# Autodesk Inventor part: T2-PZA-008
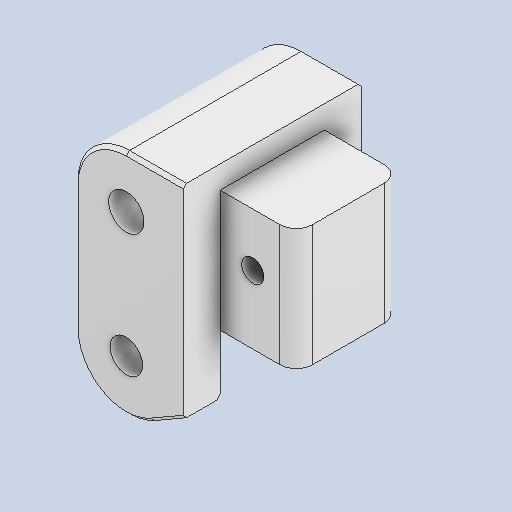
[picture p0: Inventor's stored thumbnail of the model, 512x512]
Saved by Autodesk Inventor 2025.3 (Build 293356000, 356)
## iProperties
Created: 2026-10
Part Number: T2-PZA-008
Material: Genérico
Description: Eslabón distal
Document SubType Name: Modeling
Designer: Luis MuÃ±oz
Density: 1 g/cm^3
Appearance: Valor por defecto
Project: TESIS 2 - Plataforma mecatrÃ³nica preventiva desacoplada
Sending System: ONSHAPE BY PTC INC, 1.194
Preprocessor: ST-DEVELOPER v20
Material_Fabricacion: PLA
Title: EslabÃ³n distal
Revision Number: 00
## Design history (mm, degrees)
feature "Distal_Rod"
node "Sólido1"
